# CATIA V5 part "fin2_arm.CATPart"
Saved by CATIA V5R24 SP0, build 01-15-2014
Part number: Arm
Bounding box of the stored display mesh (mm): x -0.625 to 0.625, y -5 to 16.828, z -5 to 25.625
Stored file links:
  G:\내 드라이브\04_WORK\00_LECTURE\CAD2020\exam\fin2_arm.CATPart
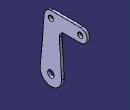
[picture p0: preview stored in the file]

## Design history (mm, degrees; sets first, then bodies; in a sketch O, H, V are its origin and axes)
Body1 (main body)
  Sketch1 on yz-plane, origin (0, 0, 0), H (0, 1, 0), V (0, 0, 1)
    construction line L1 (0, 85.7424) -> (0, -89.8746)
    point P1 (0, 85.7424)
    construction line L2 (-67.3525, 0) -> (136.7709, 0)
    construction line L3 (-64.8732, 22.5) -> (146.2747, 22.5)
    construction line L4 (13.75, 35.6074) -> (13.75, -85.465)
    arc A1 centre (0, 0) radius 5 from (-5, 0) to (5, 0) ccw
    point P9 (-5, 0)
    point P10 (5, 0)
    arc A2 centre (0, 22.5) radius 3.125 from (0, 25.625) to (-3.125, 22.5) ccw
    point P11 (0, 22.5)
    point P12 (-3.125, 22.5)
    point P13 (0, 25.625)
    line L5 (-3.125, 22.5) -> (-5, 0)
    point P14 (-3.125, 22.5)
    point P15 (-5, 0)
    arc A3 centre (13.75, 22.5) radius 3.125 from (13.75, 19.375) to (13.75, 25.625) ccw
    point P16 (13.75, 22.5)
    point P17 (13.75, 25.625)
    point P18 (13.75, 19.375)
    line L6 (0, 25.625) -> (13.75, 25.625)
    point P19 (13.75, 25.625)
    axis line L7 (5, -4.0857) -> (5, 20.2522)
    line L8 (5, 0) -> (3.6452, 19.375)
    line L9 (13.75, 19.375) -> (3.6452, 19.375)
    circle A4 centre (13.75, 22.5) radius 1.25
    circle A5 centre (0, 22.5) radius 1.25
    circle A6 centre (0, 0) radius 1.6
    distance L1 L4 = 13.75
    distance L2 L3 = 22.5
    radius A1 = 5
    radius A2 = 3.125
    radius A3 = 3.125
    angle L8 L7 = 4
    radius A5 = 1.25
    radius A4 = 1.25
    radius A6 = 1.6
    coincidence: P1 V, L2 H, P9 L2, P10 L2, P11 L3, P11 L1, P12 L3, P13 L1, P12 P14, P9 P15, P16 L4, P16 L3, P17 L4, P19 L4, L7 P10, P18 L4
    vertical: L1 V, L4 V, L7 V
    horizontal: L2 H, L3 H, L9 H
    tangency: L6 A2
  Pad1: profile Sketch1, direction (1, 0, 0), length 0.625, mirrored extent
  Fillet1: radius 2.5, on edge [face of Pad1 from Sketch1.L9 | face of Pad1 from Sketch1.L8]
